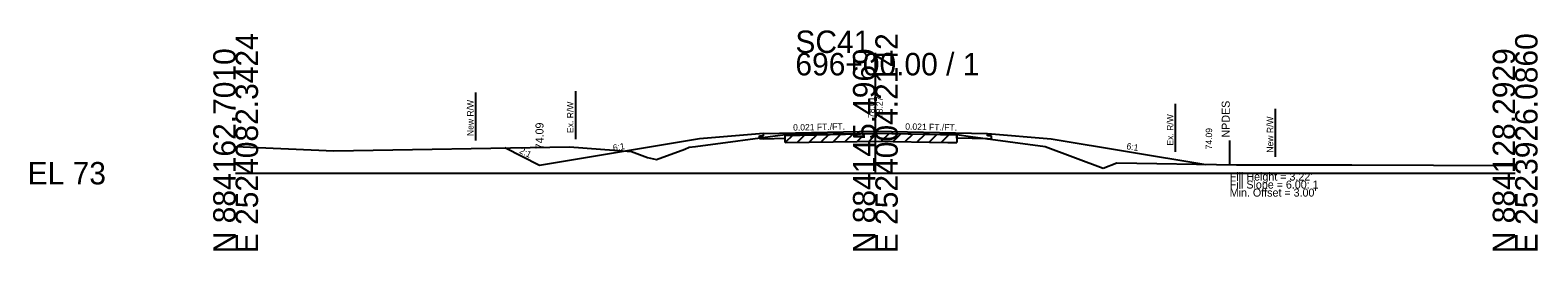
# Model space of a CAD drawing. Extents: x -26 to 183, y -10 to 24021.
# Drawn here: x -25.7 to 162.8, y 19990.3 to 20017.9 of the extents above; entities that cross this region are included whole.
import ezdxf

# ---------------------------------------------------------------- set-up
doc = ezdxf.new("R2010")
doc.units = 0
for name, color, linetype in [('RD_GPK_XS_Cell', 7, 'Continuous'), ('RD_XS_Base', 7, 'Continuous'), ('RD_XS_Buildup', 7, 'Continuous'), ('RD_XS_EarthShd', 7, 'Continuous'), ('RD_XS_ExGround', 7, 'Continuous'), ('RD_XS_ExPaveRet', 7, 'Continuous'), ('RD_XS_ExRW', 7, 'Continuous'), ('RD_XS_NewRW', 7, 'Continuous'), ('RD_XS_NPDES', 7, 'Continuous'), ('RD_XS_Pave', 7, 'Continuous'), ('RD_XS_TieSlope', 7, 'Continuous'), ('RD_XS_TX_Elev_EX', 7, 'Continuous'), ('RD_XS_TX_Elev_PR', 7, 'Continuous'), ('RD_XS_TX_Slope', 7, 'Continuous'), ('RD_XS_TX_Warning', 7, 'Continuous')]:
    doc.layers.add(name, color=color, linetype=linetype)

msp = doc.modelspace()

# ---------------------------------------------------------------- linework, layer by layer
at = {"layer": 'RD_GPK_XS_Cell'}
for p, q in [((80, 20000), (80, 20015.02)), ((0, 20000), (80, 20000)), ((80, 20000), (160, 20000))]:
    msp.add_line(p, q, dxfattribs=at)
at = {"layer": 'RD_XS_Base'}
for p, q in [((66, 20004.3), (68.73, 20004.36)), ((68.73, 20004.36), (68.73, 20004.72)), ((90.2, 20004.38), (90.2, 20004.74)), ((94, 20004.3), (90.2, 20004.38))]:
    msp.add_line(p, q, dxfattribs=at)
at = {"layer": 'RD_XS_Buildup'}
for p, q in [((68.73, 20004.72), (80, 20004.95)), ((68.73, 20004.82), (68.73, 20004.83)), ((90.2, 20004.74), (80, 20004.95))]:
    msp.add_line(p, q, dxfattribs=at)
at = {"layer": 'RD_XS_EarthShd'}
for p, q in [((66, 20004.98), (58, 20004.31)), ((94, 20004.98), (102, 20004.31))]:
    msp.add_line(p, q, dxfattribs=at)
at = {"layer": 'RD_XS_ExGround'}
for p, q in [((0, 20003.33), (12.3, 20002.78)), ((56.73, 20003.27), (57.52, 20003.35)), ((57.52, 20003.35), (68.73, 20004.82)), ((68.73, 20004.82), (77.71, 20004.97)), ((77.71, 20004.97), (79.92, 20005.01)), ((79.92, 20005.01), (89.06, 20004.84)), ((89.06, 20004.84), (90.2, 20004.82)), ((90.2, 20004.82), (91.88, 20004.59)), ((91.88, 20004.59), (101.23, 20003.33)), ((101.23, 20003.33), (108.48, 20000.63)), ((12.3, 20002.78), (41.75, 20003.29)), ((41.75, 20003.29), (49.51, 20002.71)), ((49.51, 20002.71), (51.51, 20001.95)), ((51.51, 20001.95), (52.64, 20001.72)), ((52.64, 20001.72), (56.16, 20003.01)), ((56.16, 20003.01), (56.73, 20003.27)), ((108.48, 20000.63), (110.21, 20001.29)), ((110.21, 20001.29), (125.14, 20001.03)), ((125.14, 20001.03), (139.57, 20001.03)), ((139.57, 20001.03), (160, 20000.97))]:
    msp.add_line(p, q, dxfattribs=at)
at = {"layer": 'RD_XS_ExPaveRet'}
for p, q in [((68.73, 20003.82), (69.75, 20004.84)), ((68.73, 20003.82), (68.73, 20004.82)), ((68.73, 20003.82), (77.71, 20003.97)), ((70.23, 20003.85), (71.25, 20004.87)), ((71.73, 20003.87), (72.75, 20004.89)), ((73.23, 20003.9), (74.25, 20004.92)), ((74.73, 20003.92), (75.75, 20004.94)), ((76.23, 20003.95), (77.25, 20004.97)), ((77.71, 20003.97), (79.92, 20004.01)), ((77.73, 20003.97), (78.75, 20004.99)), ((79.23, 20004), (80.24, 20005)), ((79.92, 20004.01), (89.06, 20003.84)), ((80.73, 20003.99), (81.72, 20004.97)), ((82.23, 20003.96), (83.22, 20004.95)), ((83.73, 20003.94), (84.72, 20004.92)), ((85.23, 20003.91), (86.22, 20004.89)), ((86.73, 20003.88), (87.72, 20004.86)), ((88.23, 20003.85), (89.22, 20004.84)), ((89.06, 20003.84), (90.2, 20003.82)), ((90.2, 20004.82), (90.2, 20003.82))]:
    msp.add_line(p, q, dxfattribs=at)
at = {"layer": 'RD_XS_ExRW'}
for p, q in [((42.5, 20010.24), (42.5, 20004.24)), ((117.5, 20008.66), (117.5, 20002.66))]:
    msp.add_line(p, q, dxfattribs=at)
at = {"layer": 'RD_XS_NewRW'}
for p, q in [((30, 20010.09), (30, 20004.09)), ((130, 20008.03), (130, 20002.03))]:
    msp.add_line(p, q, dxfattribs=at)
at = {"layer": 'RD_XS_NPDES'}
msp.add_line((124.31, 20001.08), (124.31, 20004.08), dxfattribs=at)
at = {"layer": 'RD_XS_Pave'}
for p, q in [((66, 20004.98), (80, 20005.27)), ((80, 20005.27), (94, 20004.98)), ((65.5, 20004.65), (66, 20004.66)), ((65.5, 20004.29), (65.5, 20004.65)), ((66, 20004.3), (65.5, 20004.29)), ((66, 20004.66), (66, 20004.98)), ((94, 20004.66), (94, 20004.98)), ((94.5, 20004.65), (94, 20004.66)), ((94, 20004.3), (94.5, 20004.29)), ((94.5, 20004.29), (94.5, 20004.65))]:
    msp.add_line(p, q, dxfattribs=at)
at = {"layer": 'RD_XS_TieSlope'}
for p, q in [((58, 20004.31), (38, 20000.98)), ((102, 20004.31), (121.31, 20001.09)), ((38, 20000.98), (33.66, 20003.15))]:
    msp.add_line(p, q, dxfattribs=at)

# ---------------------------------------------------------------- texts
at = {"layer": 'RD_GPK_XS_Cell'}
for s, p in [('E 2524082.3424', (2.8, 19990)), ('E 2524004.2142', (82.8, 19990)), ('E 2523926.0860', (162.8, 19990)), ('N 884162.7010', (0, 19990)), ('N 884145.4969', (80, 19990)), ('N 884128.2929', (160, 19990))]:
    msp.add_text(s, height=2.8, rotation=90, dxfattribs=at).set_placement(p)
for s, p in [('SC41', (70, 20015.02)), ('696+00.00 / 1', (70, 20012.22)), ('EL 73', (-26, 19998.6))]:
    msp.add_text(s, height=2.8, dxfattribs=at).set_placement(p)
at = {"layer": 'RD_XS_ExRW'}
for p in [(42.25, 20005.02), (117.25, 20003.45)]:
    msp.add_text('Ex. R/W ', height=0.8, rotation=90, dxfattribs=at).set_placement(p)
at = {"layer": 'RD_XS_NewRW'}
for p in [(29.75, 20004.64), (129.75, 20002.57)]:
    msp.add_text('New R/W ', height=0.8, rotation=90, dxfattribs=at).set_placement(p)
at = {"layer": 'RD_XS_TX_Elev_EX'}
msp.add_text('78.01', height=0.8, rotation=90, dxfattribs=at).set_placement((79.9, 20006.89))
at = {"layer": 'RD_XS_TX_Elev_PR'}
for s, height, p in [('78.27', 0.8, (80.9, 20006.89)), ('74.09', 1, (38.5, 20002.98)), ('74.09', 0.8, (122.11, 20002.97))]:
    msp.add_text(s, height=height, rotation=90, dxfattribs=at).set_placement(p)
at = {"layer": 'RD_XS_TX_Slope'}
for s, rotation, p in [('0.021 FT./FT.', 1.1916, (69.72, 20005.31)), ('0.021 FT./FT.', 358.8084, (83.73, 20005.44)), ('6:1', 9.4623, (47.25, 20002.77)), ('6:1', 350.5377, (111.36, 20003.01)), ('2:1', 333.4349, (35.41, 20002.56))]:
    msp.add_text(s, height=0.8, rotation=rotation, dxfattribs=at).set_placement(p)
at = {"layer": 'RD_XS_TX_Warning'}
msp.add_text(' NPDES', height=1, rotation=90, dxfattribs=at).set_placement((124.31, 20004.08))
for s, p in [("Fill Height = 3.22' ", (124.31, 19999.08)), ('Fill Slope = 6.00: 1', (124.31, 19998.08)), ("Min. Offset = 3.00' ", (124.31, 19997.08))]:
    msp.add_text(s, height=1, dxfattribs=at).set_placement(p)

doc.saveas('drawing.dxf')
